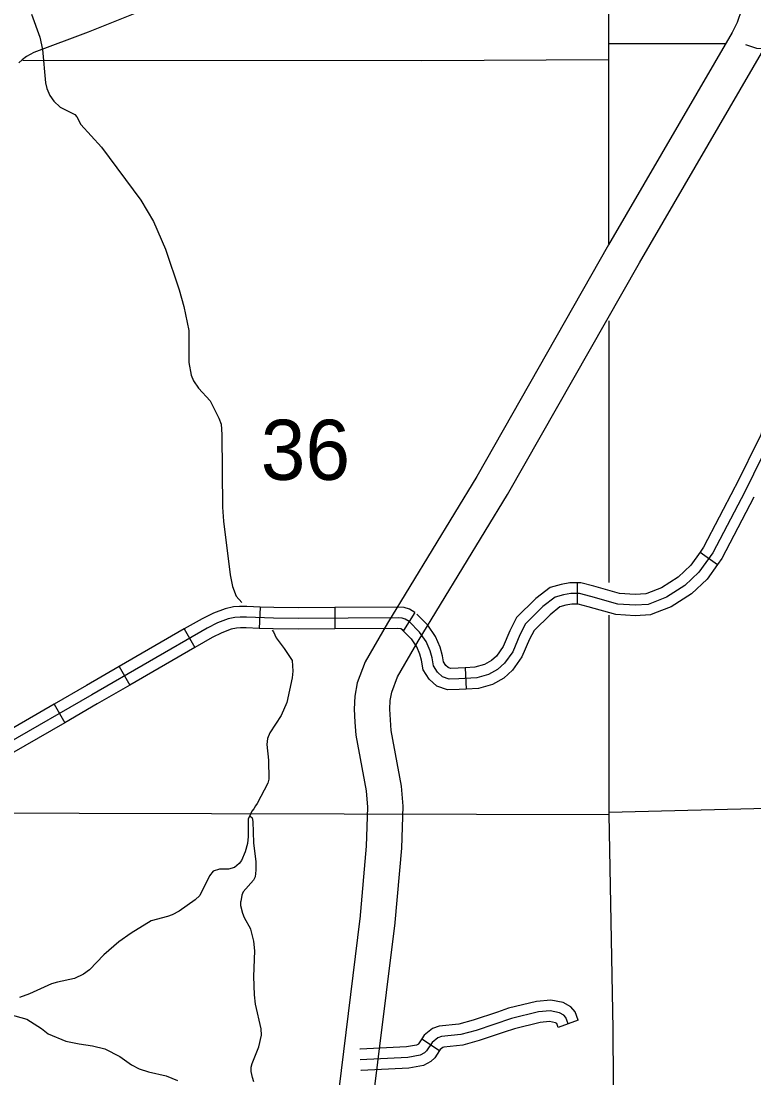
# Model space of a CAD drawing. Extents: x 1373862 to 1376999, y 1168398 to 1170455.
# Drawn here: x 1374848.9 to 1374951.9, y 1168749.6 to 1168898.2 of the extents above; entities that cross this region are included whole.
import ezdxf

# ---------------------------------------------------------------- set-up
doc = ezdxf.new("R2010")
doc.units = 0
for name, color, linetype in [('Level 10', 7, 'Continuous'), ('Level 32', 7, 'Continuous'), ('Level 35', 7, 'Continuous'), ('Level 4', 7, 'Continuous'), ('Level 45', 7, 'Continuous'), ('Level 5', 7, 'Continuous')]:
    doc.layers.add(name, color=color, linetype=linetype)

msp = doc.modelspace()

# ---------------------------------------------------------------- linework, layer by layer
at = {"layer": 'Level 10'}
for points in [[(1374950.78, 1168902.62), (1374950.6, 1168901.45), (1374950.19, 1168899.8), (1374949.54, 1168897.99), (1374948.88, 1168896.59), (1374931.47, 1168866.72), (1374912.95, 1168834.16), (1374900.38, 1168813.55), (1374897.26, 1168808.12), (1374896.16, 1168805.15), (1374895.82, 1168803.27), (1374895.72, 1168801.48), (1374895.81, 1168799.61), (1374895.97, 1168797.8), (1374897.4, 1168789.98), (1374897.58, 1168787.68), (1374897.41, 1168782.21), (1374896.5, 1168771.93)], [(1374901.48, 1168771.48), (1374902.41, 1168781.91), (1374902.59, 1168787.8), (1374902.37, 1168790.62), (1374900.93, 1168798.47), (1374900.8, 1168799.94), (1374900.73, 1168801.46), (1374900.79, 1168802.68), (1374901, 1168803.83), (1374901.8, 1168805.99), (1374904.69, 1168811), (1374917.26, 1168831.62), (1374935.81, 1168864.23), (1374953.32, 1168894.26), (1374954.17, 1168896.09), (1374954.98, 1168898.35), (1374955.51, 1168900.45), (1374955.72, 1168901.85)], [(1374867.44, 1168900.3), (1374858.32, 1168896.62), (1374850.69, 1168893.77), (1374849.67, 1168893.24), (1374849.03, 1168892.77), (1374848.57, 1168892.33)], [(1374896.51, 1168772.01), (1374892.88, 1168742.63), (1374891.63, 1168732.35), (1374891.02, 1168727.2), (1374891.09, 1168723.76), (1374891.45, 1168721.65), (1374892.49, 1168718.72), (1374894.96, 1168712.81), (1374899.98, 1168701.97), (1374903.27, 1168695.8), (1374906.32, 1168691.35), (1374909.85, 1168687.7), (1374917.89, 1168680.79), (1374925.83, 1168673.48), (1374927.17, 1168671.58), (1374927.71, 1168670.52), (1374927.87, 1168670.01), (1374928.37, 1168658.67), (1374928.39, 1168657.97)], [(1374933.39, 1168658.06), (1374933.37, 1168658.82), (1374932.84, 1168670.9), (1374932.35, 1168672.42), (1374931.47, 1168674.17), (1374929.61, 1168676.8), (1374921.22, 1168684.52), (1374913.28, 1168691.35), (1374910.2, 1168694.52), (1374907.56, 1168698.4), (1374904.46, 1168704.2), (1374899.54, 1168714.83), (1374897.16, 1168720.52), (1374896.31, 1168722.92), (1374896.08, 1168724.24), (1374896.03, 1168726.95), (1374896.6, 1168731.75), (1374897.84, 1168742.03), (1374901.47, 1168771.4)]]:
    msp.add_lwpolyline(points, dxfattribs=at)
at = {"layer": 'Level 32'}
for p, q in [((1374882.52, 1168815.81), (1374882.38, 1168812.82)), ((1374893, 1168815.73), (1374893.01, 1168812.73)), ((1374904.24, 1168815.05), (1374902.65, 1168812.5)), ((1374871.82, 1168812.73), (1374873.32, 1168810.13)), ((1374862.67, 1168807.45), (1374864.17, 1168804.85)), ((1374853.53, 1168802.16), (1374855.03, 1168799.56))]:
    msp.add_line(p, q, dxfattribs=at)
for points in [[(1374882.52, 1168815.81), (1374880.61, 1168815.9), (1374879.61, 1168815.9), (1374878.73, 1168815.83), (1374877.56, 1168815.58), (1374875.92, 1168814.96), (1374874.33, 1168814.18), (1374871.82, 1168812.73)], [(1374893, 1168815.73), (1374887.84, 1168815.7), (1374884.43, 1168815.73), (1374882.52, 1168815.81)], [(1374904.24, 1168815.05), (1374903.51, 1168815.51), (1374902.75, 1168815.73), (1374901.94, 1168815.78), (1374893, 1168815.73)], [(1374903.45, 1168813.78), (1374902.89, 1168814.12), (1374902.48, 1168814.24), (1374901.88, 1168814.28), (1374887.83, 1168814.2), (1374884.39, 1168814.23), (1374880.57, 1168814.4), (1374879.67, 1168814.4), (1374878.94, 1168814.34), (1374877.98, 1168814.14), (1374876.52, 1168813.58), (1374875.04, 1168812.86), (1374858.83, 1168803.49), (1374846.79, 1168796.52)], [(1374871.82, 1168812.73), (1374862.67, 1168807.45)], [(1374882.38, 1168812.82), (1374880.54, 1168812.9), (1374879.73, 1168812.9), (1374879.16, 1168812.86), (1374878.41, 1168812.7), (1374877.12, 1168812.21), (1374875.74, 1168811.53), (1374873.32, 1168810.13)], [(1374893.01, 1168812.73), (1374887.83, 1168812.7), (1374884.35, 1168812.73), (1374882.38, 1168812.82)], [(1374902.65, 1168812.5), (1374902.28, 1168812.74), (1374902.22, 1168812.76), (1374901.83, 1168812.78), (1374893.01, 1168812.73)], [(1374873.32, 1168810.13), (1374864.17, 1168804.85)], [(1374862.67, 1168807.45), (1374858.08, 1168804.79), (1374853.53, 1168802.16)], [(1374864.17, 1168804.85), (1374859.58, 1168802.19), (1374855.03, 1168799.56)], [(1374853.53, 1168802.16), (1374846.03, 1168797.81), (1374844.39, 1168796.83)], [(1374855.03, 1168799.56), (1374847.55, 1168795.23), (1374845.93, 1168794.26)]]:
    msp.add_lwpolyline(points, dxfattribs=at)
at = {"layer": 'Level 35'}
for points in [[(1374850.37, 1168899.18), (1374851.5, 1168895.95), (1374851.91, 1168894.19), (1374852.34, 1168889.53), (1374852.51, 1168888.73), (1374852.92, 1168887.73), (1374853.48, 1168886.94), (1374854.37, 1168886.11), (1374856.42, 1168885.08), (1374856.73, 1168884.74), (1374857.28, 1168883.67), (1374860.17, 1168880.47), (1374865.7, 1168873), (1374867.51, 1168870.02), (1374869.21, 1168866.13), (1374871.13, 1168860.39), (1374871.77, 1168858.06), (1374872.48, 1168854.7), (1374872.49, 1168850.19), (1374872.81, 1168848.43), (1374873.15, 1168847.61), (1374873.82, 1168846.58), (1374875.45, 1168844.8), (1374876.7, 1168842.36), (1374877, 1168841.54), (1374877.1, 1168840.06), (1374877.21, 1168829.88), (1374877.36, 1168827.9)], [(1374877.36, 1168827.9), (1374878.28, 1168820.33), (1374878.62, 1168818.72), (1374879.14, 1168817.36), (1374879.93, 1168816.47)], [(1374884.2, 1168812.56), (1374884.36, 1168812.33), (1374884.73, 1168811.47), (1374885.89, 1168809.99), (1374886.98, 1168808.3), (1374887.08, 1168806.8), (1374886.99, 1168805.88), (1374886.23, 1168802.38), (1374885.44, 1168800.56), (1374883.85, 1168798.13), (1374883.55, 1168797.35), (1374883.42, 1168796.5), (1374883.69, 1168794.3), (1374883.71, 1168791.62), (1374883.56, 1168791.05), (1374882.09, 1168788.18), (1374881.83, 1168787.89), (1374881.63, 1168787.44), (1374881.33, 1168787.14), (1374881.07, 1168786.48)], [(1374881.07, 1168786.48), (1374880.8, 1168786.04), (1374880.82, 1168783.57), (1374880.73, 1168782.57), (1374880.4, 1168781.38), (1374879.88, 1168780.2), (1374879.57, 1168779.75), (1374878.89, 1168779.18), (1374878.06, 1168778.96), (1374876.78, 1168778.97), (1374875.88, 1168778.68), (1374875.38, 1168778.03), (1374874.03, 1168775.27), (1374873.38, 1168774.66)], [(1374881.07, 1168786.48), (1374881.36, 1168786.17), (1374881.45, 1168785.67), (1374881.56, 1168782.67), (1374881.89, 1168780.01), (1374881.89, 1168778.83), (1374881.78, 1168777.9), (1374881.55, 1168777.42), (1374880.13, 1168775.76), (1374879.9, 1168775.31), (1374879.78, 1168774.41)], [(1374873.38, 1168774.66), (1374871.12, 1168773.08), (1374870.11, 1168772.56), (1374869.46, 1168772.3), (1374867.18, 1168771.7), (1374864.36, 1168769.95), (1374862.61, 1168768.73), (1374860.54, 1168766.9), (1374858.49, 1168764.8), (1374857.67, 1168764.18), (1374856.38, 1168763.59), (1374854, 1168763.09), (1374853.16, 1168762.83), (1374850.08, 1168761.42), (1374848.65, 1168760.9)], [(1374881.41, 1168749.66), (1374881.23, 1168750.54), (1374881.25, 1168751.14), (1374881.36, 1168751.66), (1374882.33, 1168753.97), (1374882.69, 1168755.62), (1374882.64, 1168756.54), (1374881.84, 1168759.97), (1374881.71, 1168761.29), (1374881.61, 1168763.89), (1374881.75, 1168767.48), (1374881.61, 1168768.86), (1374881.19, 1168770.54), (1374880.3, 1168772.12), (1374880.04, 1168772.73), (1374879.8, 1168773.81), (1374879.78, 1168774.41)], [(1374847.17, 1168758.58), (1374849.7, 1168757.88), (1374851.75, 1168756.57), (1374852.69, 1168755.83), (1374855.19, 1168754.79), (1374857.04, 1168754.41), (1374858.92, 1168754.15), (1374860.67, 1168753.71), (1374862.76, 1168752.62), (1374864.42, 1168751.46), (1374865.51, 1168750.9), (1374866.78, 1168750.47), (1374869.3, 1168749.89), (1374870.87, 1168749.25)], [(1374881.62, 1168749.08), (1374881.41, 1168749.66)]]:
    msp.add_lwpolyline(points, dxfattribs=at)
at = {"layer": 'Level 4'}
for points in [[(1374931.42, 1168904.44), (1374931.48, 1168895.02), (1374931.49, 1168892.74), (1374931.49, 1168866.89)], [(1374931.5, 1168856.06), (1374931.5, 1168819.27)], [(1374931.5, 1168814.66), (1374931.51, 1168786.97)], [(1374931.51, 1168786.97), (1375039.06, 1168789.69), (1375040.18, 1168789.72), (1375108.76, 1168790.57)], [(1374783.68, 1168787.35), (1374825.24, 1168787.11), (1374826.07, 1168787.09), (1374838.38, 1168786.89), (1374931.51, 1168786.64)], [(1374931.51, 1168786.97), (1374931.51, 1168786.64), (1374932.06, 1168756.53), (1374932.18, 1168741.4)]]:
    msp.add_lwpolyline(points, dxfattribs=at)
at = {"layer": 'Level 45'}
for p, q in [((1374944.35, 1168823.54), (1374946.79, 1168821.8)), ((1374927.08, 1168819.2), (1374927.08, 1168816.2)), ((1374911.32, 1168807.27), (1374911.48, 1168804.28)), ((1374927.22, 1168757.75), (1374924.4, 1168756.72)), ((1374905.23, 1168755.12), (1374907.73, 1168753.47))]:
    msp.add_line(p, q, dxfattribs=at)
for points in [[(1374993, 1168886.67), (1374992.5, 1168886.89), (1374992.01, 1168887.5), (1374991.23, 1168888.39), (1374989.19, 1168890.6), (1374986.76, 1168893.36), (1374985.21, 1168894.74), (1374983.95, 1168895.29), (1374982.9, 1168895.46), (1374981.74, 1168895.29), (1374978.98, 1168894.85), (1374972.85, 1168894.46), (1374955.57, 1168894.13), (1374952.33, 1168894.35), (1374950.76, 1168894.85)], [(1374953.45, 1168841.98), (1374952.88, 1168840.01), (1374949.28, 1168832.71), (1374949.25, 1168832.65)], [(1374954.29, 1168839.46), (1374950.62, 1168832.03), (1374946.12, 1168823.44), (1374944.19, 1168820.73), (1374942.22, 1168818.85), (1374939.61, 1168817.2), (1374937.04, 1168816.19), (1374935.2, 1168816.1), (1374932.77, 1168816.24), (1374929.01, 1168817.29), (1374927.4, 1168817.7), (1374926.16, 1168817.7), (1374925.15, 1168817.52), (1374923.96, 1168817.2), (1374922.26, 1168815.87), (1374919.78, 1168813.44), (1374919, 1168811.92), (1374918, 1168809.53), (1374916.85, 1168807.93), (1374915.88, 1168807.05), (1374914.6, 1168806.32), (1374912.95, 1168805.86), (1374910.42, 1168805.72), (1374909.05, 1168805.68), (1374908.13, 1168806), (1374907.44, 1168806.64), (1374906.85, 1168807.56), (1374906.66, 1168808.66), (1374906.39, 1168809.67), (1374905.84, 1168810.96), (1374904.92, 1168812.29), (1374903.45, 1168813.78)], [(1374949.25, 1168832.65), (1374944.84, 1168824.23), (1374944.35, 1168823.54)], [(1374951.91, 1168831.26), (1374947.4, 1168822.66), (1374946.79, 1168821.8)], [(1374944.35, 1168823.54), (1374943.05, 1168821.72), (1374941.29, 1168820.04), (1374938.92, 1168818.54), (1374936.86, 1168817.73)], [(1374946.79, 1168821.8), (1374945.33, 1168819.75), (1374943.15, 1168817.66), (1374940.29, 1168815.86), (1374937.95, 1168814.94)], [(1374927.08, 1168819.2), (1374926.03, 1168819.2), (1374924.82, 1168818.99), (1374923.27, 1168818.57), (1374921.27, 1168817), (1374918.56, 1168814.34), (1374917.65, 1168812.56), (1374917.6, 1168812.46)], [(1374936.86, 1168817.73), (1374936.72, 1168817.68), (1374935.21, 1168817.6), (1374933.02, 1168817.72), (1374929.4, 1168818.74), (1374927.59, 1168819.2), (1374927.08, 1168819.2)], [(1374927.08, 1168816.2), (1374926.3, 1168816.2), (1374925.48, 1168816.06), (1374924.65, 1168815.83), (1374923.25, 1168814.74), (1374921.01, 1168812.53), (1374920.36, 1168811.28), (1374920.37, 1168811.29)], [(1374937.95, 1168814.94), (1374937.36, 1168814.7), (1374935.2, 1168814.6), (1374932.52, 1168814.75), (1374928.62, 1168815.84), (1374927.21, 1168816.2), (1374927.08, 1168816.2)], [(1374905.97, 1168813.36), (1374904.51, 1168814.83)], [(1374903.84, 1168811.25), (1374902.38, 1168812.72)], [(1374911.32, 1168807.27), (1374910.36, 1168807.22), (1374909.28, 1168807.19), (1374908.92, 1168807.31), (1374908.6, 1168807.61), (1374908.27, 1168808.11), (1374908.13, 1168808.98), (1374907.81, 1168810.17), (1374907.16, 1168811.68), (1374906.08, 1168813.25), (1374905.97, 1168813.36)], [(1374917.6, 1168812.46), (1374916.68, 1168810.27), (1374915.72, 1168808.93), (1374915, 1168808.28), (1374914.02, 1168807.72), (1374912.7, 1168807.35), (1374911.32, 1168807.27)], [(1374911.48, 1168804.28), (1374910.49, 1168804.22), (1374908.82, 1168804.17), (1374907.34, 1168804.69), (1374906.28, 1168805.67), (1374905.42, 1168807), (1374905.2, 1168808.34), (1374904.97, 1168809.18), (1374904.52, 1168810.23), (1374903.76, 1168811.33), (1374903.84, 1168811.25)], [(1374920.37, 1168811.29), (1374919.31, 1168808.8), (1374917.98, 1168806.92), (1374916.77, 1168805.83), (1374915.18, 1168804.93), (1374913.19, 1168804.37), (1374911.48, 1168804.28)], [(1374927.22, 1168757.75), (1374926.8, 1168758.9), (1374926.16, 1168759.6), (1374925.12, 1168760.21), (1374923.35, 1168760.57), (1374921.36, 1168760.38), (1374917.42, 1168759.41), (1374915.86, 1168758.88)], [(1374925.81, 1168757.24), (1374925.49, 1168758.11), (1374925.2, 1168758.42), (1374924.58, 1168758.79), (1374923.27, 1168759.06), (1374921.62, 1168758.9), (1374917.84, 1168757.97), (1374912.87, 1168756.3), (1374910.72, 1168755.71), (1374907.99, 1168755.43), (1374907.46, 1168755.23), (1374906.69, 1168754.61), (1374905.9, 1168753.41), (1374905.61, 1168753.15), (1374904.98, 1168752.81), (1374903.25, 1168752.49), (1374896.57, 1168752.16)], [(1374915.86, 1168758.88), (1374912.43, 1168757.74), (1374910.44, 1168757.19), (1374907.65, 1168756.9), (1374906.71, 1168756.56), (1374905.57, 1168755.63), (1374905.23, 1168755.12)], [(1374924.4, 1168756.72), (1374924.2, 1168757.27), (1374924.03, 1168757.37), (1374923.19, 1168757.54), (1374921.87, 1168757.42), (1374918.26, 1168756.52), (1374916.81, 1168756.04)], [(1374916.81, 1168756.04), (1374913.3, 1168754.87), (1374911, 1168754.23), (1374908.33, 1168753.95), (1374908.2, 1168753.91), (1374907.82, 1168753.59), (1374907.73, 1168753.47)], [(1374905.23, 1168755.12), (1374904.75, 1168754.39), (1374904.74, 1168754.38), (1374904.48, 1168754.24), (1374903.07, 1168753.98), (1374896.55, 1168753.66)], [(1374896.55, 1168753.66), (1374896.5, 1168753.66)], [(1374907.73, 1168753.47), (1374907.05, 1168752.43), (1374906.48, 1168751.91), (1374905.48, 1168751.38), (1374903.42, 1168750.99), (1374896.69, 1168750.67)], [(1374896.69, 1168750.67), (1374896.65, 1168750.66)]]:
    msp.add_lwpolyline(points, dxfattribs=at)
at = {"layer": 'Level 5'}
for points in [[(1374947.96, 1168895.01), (1374931.48, 1168895.02)], [(1374931.49, 1168892.74), (1374905.24, 1168892.62), (1374849.11, 1168892.67)]]:
    msp.add_lwpolyline(points, dxfattribs=at)

# ---------------------------------------------------------------- texts
msp.add_text('36', height=8.448, dxfattribs=at).set_placement((1374882.58, 1168833.7))

doc.saveas('drawing.dxf')
